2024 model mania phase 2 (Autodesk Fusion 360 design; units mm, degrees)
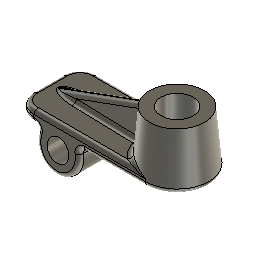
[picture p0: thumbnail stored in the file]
sketch "Sketch1" plane through (0, 0, 0) normal (0, 0, 1) x axis (1, 0, 0)
  line L1 (70, 40) -> (10, 40)
  line L2 (10, 10) -> (70, 10)
  line L3 (10, 40) -> (10, 10)
  arc A1 centre (70, 25) radius 15 clockwise from (70, 40) to (70, 10)
  point P2 (10, 40)
  point P3 (10, 10)
  point P1 (0, 0)
  point P4 (70, 25)
  horizontal L1
  horizontal L2
  vertical L3
  tangent L2 A1
  dimension "d2" distance P2 P3 = 30
  dimension "d3" distance P1 L2 = 10
  dimension "d4" distance P1 L3 = 10
  dimension "d38" diameter A1 = 30
  dimension "d39" distance L3 P4 = 60
extrude "Extrude1" new body sketch "Sketch1" profile of L1 L2 L3 along normal blind 5
sketch "Sketch2" plane through (0, 0, 5) normal (0, 0, 1) x axis (-1, 0, 0)
  line L1 (-70, -10) -> (-10, -10)
  line L2 (-10, -40) -> (-70, -40)
  line L3 (-10, -10) -> (-10, -40)
  circle C1 centre (-70, -25) radius 7.5
  circle C2 centre (-70, -25) radius 15
  arc A1 centre (-70, -25) radius 15 clockwise from (-70, -40) to (-70, -10)
  point P6 (-70, -25)
  point P7 (-70, -25)
  concentric C1 C2
  tangent L2 C2
  dimension "d7" diameter C1 = 15
  dimension "d9" distance L2 P6 = 15
  dimension "d17" distance L3 P7 = 60
extrude "Extrude2" cut sketch "Sketch2" profile of C1 against normal blind 5
extrude "Extrude3" add sketch "Sketch2" profile of C1 C2 A1 along normal blind 20
work_plane "WorkPlane1"
sketch "Sketch3" plane through (0, 25, 0) normal (0, 1, 0) x axis (1, 0, 0)
  line L1 (57, -20) -> (57, -5)
  line L2 (85, -25) -> (55, -25)
  line L3 (77.5, 0) -> (62.5, 0)
  line L4 (10, 0) -> (70, 0)
  line L5 (70, 0) -> (10, 0)
  line L6 (56, -20) -> (57, -20)
  line L7 (15, -5) -> (56, -20)
  line L8 (55, -5) -> (70, -5)
  line L9 (10, -5) -> (70, -5)
  line L10 (70, -5) -> (10, -5)
  line L11 (55, -5) -> (70, -5)
  line L12 (70, 0) -> (70, -5)
  line L13 (85, 0) -> (70, 0)
  line L14 (70, -5) -> (70, 0)
  line L15 (85, 0) -> (70, 0)
  circle C1 centre (30, 5) radius 5
  arc A1 centre (30, 5) radius 10 clockwise from (21.3397, 0) to (38.6603, 0)
  point P15 (38.6603, 0)
  point P16 (21.3397, 0)
  point P18 (15, -5)
  point P3 (57, -5)
  point P17 (56, -20)
  point P28 (56, -20)
  point P8 (30, 5)
  point P10 (10, 0)
  point P23 (10, -5)
  point P4 (57, -20)
  point P20 (55, -5)
  concentric C1 A1
  coincident L4 P15
  coincident L4 P16
  coincident P18 L10
  coincident P3 L9
  coincident P17 P28
  dimension "d19" diameter C1 = 10
  dimension "d20" diameter A1 = 20
  dimension "d21" distance P8 P10 = 20
  dimension "d27" distance P18 P23 = 5
  dimension "d28" distance P4 L10 = 15
  dimension "d29" angle L1 L6 = 90
  dimension "d30" angle L1 L10 = 90
  dimension "d31" distance P3 P20 = 2
  dimension "d40" distance P4 P28 = 1
extrude "Extrude7" add sketch "Sketch3" profile of L1 L6 L7 L8 L9 L10 L11 distance 2
extrude "Extrude5" add sketch "Sketch3" profile of C1 A1 L4 L5 distance 15
draft "Draft2" Angle1 5 Angle2 0
draft "Draft3" Angle1 5 Angle2 0
fillet "Fillet1" radius 8
draft "Draft1" Angle1 -5 Angle2 0
fillet "Fillet10" radius 2
fillet "Fillet13" radius 2
fillet "Fillet14" radius 2
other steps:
create_component "CreateComponent1"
